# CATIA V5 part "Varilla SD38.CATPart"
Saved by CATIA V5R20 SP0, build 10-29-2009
Part number: Varilla SD38
Revision: ANY
Definition: UNKNOWN
Nomenclature: Varilla SD38
Source: Unknown
Bounding box of the stored display mesh (mm): x -5.85 to 5.85, y 0 to 210, z -6 to 6
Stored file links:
  C:\Users\Utente\Desktop\IO LAVORO\3D X SITO CF\CUMSA\3D files SD\SD 3824\Varilla SD38.CATPart
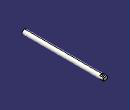
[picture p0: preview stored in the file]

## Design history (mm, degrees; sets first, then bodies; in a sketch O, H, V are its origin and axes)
Body1 "Cortar-Extruir2" (main body)
  Solid1: solid without history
